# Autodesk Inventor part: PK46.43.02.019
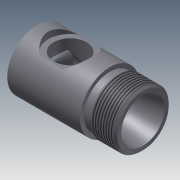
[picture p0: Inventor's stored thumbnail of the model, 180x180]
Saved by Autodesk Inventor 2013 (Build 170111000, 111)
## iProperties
Shininess: 64.0
Length Units: 11269
Angle Units: 11279
Time Units: 11290
Mass Units: 11283
Length Display Precision: 3
Angle Display Precision: 2
Created: 2002-03
Part Number: PK46.43.02.019
Material: Steel, Mild
Document SubType Name: Modeling
Designer: TEvgeniy
Density: 1 g/cm^3
Density: 0.0
Volumn: 0.0
Area: 0.0
PropertySet Name: Model Information
Control State: 0
Master: False
Checked Out: False
Checked Out Date: 2008-10-09
Last Check In Date: 2008-10-09
Author: TEvgeniy
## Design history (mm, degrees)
node "WorkPlane2"
node "WorkPlane1"
sketch "Sketch1"
  geometry: L1 (80, 19.4)-(80, 16.5); L2 (78.4, 21)-(80, 19.4); L3 (78.4, 21)-(61.5, 21); L4 (60, 19.5)-(61.5, 21); L5 (55, 19.5)-(60, 19.5); L6 (55, 22.5)-(55, 19.5); L7 (0, 22.5)-(55, 22.5); L8 through (0, 11.25) direction (0, -1); L9 through (3.892, 0) direction (1, 0); L10 (15, 12.5)-(7.783, 0); L11 (15, 12.5)-(61.181, 12.5); L12 (80, 16.5)-(61.181, 12.5); L13 through (3.892, 0) direction (1, 0)
  constraints: 23 end point, 7 horizontal, 4 vertical, 2 other
revolve "RevolutionAngle1" sketch "Sketch1" stored, may be unused: angle "d0" = 360 deg
sketch "Sketch2"
  geometry: L1 (0, -22.5)-(0, 22.5) reference; C1 r 16.5 at (25, 0)
  constraints: 1 centre point
  dimensions: "d2" = 33 diameter of C1; "d11" = 25 distance from line of L1 C1.centre
extrude "ExtrusionBlind1" cut sketch "Sketch2" distance "d3" = 5; taper "d4" = 0 deg
sketch "Sketch3"
  geometry: L1 (0, -22.5)-(0, 22.5) reference; C1 r 12.5 at (25, 0)
  constraints: 1 centre point
  dimensions: "d7" = 25 diameter of C1; "d10" = 25 distance from line of L1 C1.centre
extrude "ExtrusionBlind2" cut sketch "Sketch3" distance "d8" = 17.5; taper "d9" = 0 deg
thread "Thread1" dims "d12" = 10, "d13" = 0
body "Solid1"
other parameters: "d1" = 33 (derived), "d5" = 0, "d6" = 25 (derived)
